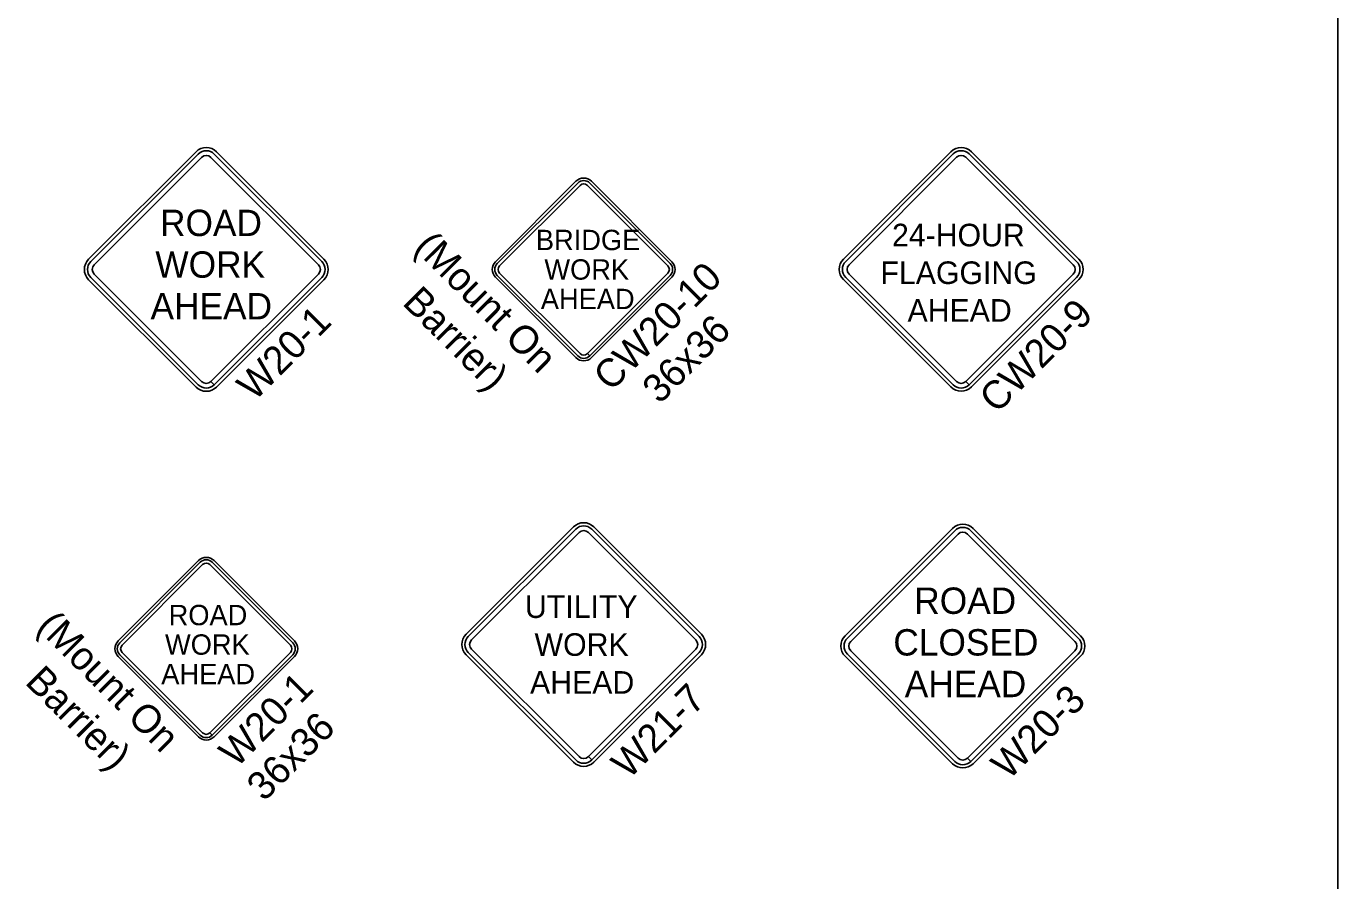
# Model space of a CAD drawing. Extents: x 1458 to 4498, y 17709 to 24109.
# Drawn here: x 2883 to 3578, y 22648 to 23102 of the extents above; entities that cross this region are included whole.
import ezdxf

# ---------------------------------------------------------------- set-up
doc = ezdxf.new("R2010")
doc.units = 0
doc.layers.add('P_ODOT_PLAN_TBlock', color=7, linetype='Continuous')
doc.layers.add('P_TRAF_TCP_General', color=7, linetype='Continuous')

msp = doc.modelspace()

# ---------------------------------------------------------------- linework, layer by layer
at = {"layer": 'P_ODOT_PLAN_TBlock'}
msp.add_line((3578.44, 23153.55), (3578.44, 22109.14), dxfattribs=at)
at = {"layer": 'P_TRAF_TCP_General'}
for p, q in [((2972.81, 23035.32), (2915.81, 22978.32)), ((3040.67, 22978.32), (2983.66, 23035.32)), ((3373.24, 23035.37), (3316.23, 22978.36)), ((3441.09, 22978.36), (3384.09, 23035.37)), ((2974, 23034.14), (2916.99, 22977.13)), ((2974, 23034.14), (2916.99, 22977.13)), ((2974, 23034.14), (2916.99, 22977.13)), ((2918.76, 22975.37), (2975.76, 23032.37)), ((2918.76, 22975.37), (2975.76, 23032.37)), ((2980.71, 23032.37), (3037.72, 22975.37)), ((2980.71, 23032.37), (3037.72, 22975.37)), ((3039.49, 22977.13), (2982.48, 23034.14)), ((3039.49, 22977.13), (2982.48, 23034.14)), ((3039.49, 22977.13), (2982.48, 23034.14)), ((3374.42, 23034.18), (3317.42, 22977.18)), ((3319.18, 22975.41), (3376.19, 23032.42)), ((3381.14, 23032.42), (3438.14, 22975.41)), ((3439.91, 22977.18), (3382.9, 23034.18)), ((3174.34, 23019.69), (3131.65, 22977)), ((3175.26, 23018.77), (3132.56, 22976.08)), ((3175.26, 23018.77), (3132.56, 22976.08)), ((3133.8, 22974.84), (3176.49, 23017.53)), ((3180.38, 23017.53), (3223.07, 22974.84)), ((3224.31, 22976.08), (3181.62, 23018.77)), ((3224.31, 22976.08), (3181.62, 23018.77)), ((3225.23, 22977), (3182.54, 23019.69)), ((2915.81, 22967.47), (2972.81, 22910.46)), ((2916.99, 22968.65), (2974, 22911.65)), ((2916.99, 22968.65), (2974, 22911.65)), ((2916.99, 22968.65), (2974, 22911.65)), ((2975.76, 22913.41), (2918.76, 22970.42)), ((2975.76, 22913.41), (2918.76, 22970.42)), ((3037.72, 22970.42), (2980.73, 22913.43)), ((3037.72, 22970.42), (2980.73, 22913.43)), ((2982.48, 22911.65), (3039.49, 22968.65)), ((2982.5, 22911.66), (3039.49, 22968.65)), ((2982.5, 22911.66), (3039.49, 22968.65)), ((2983.66, 22910.46), (3040.67, 22967.47)), ((3131.65, 22968.8), (3174.34, 22926.1)), ((3132.56, 22969.72), (3175.26, 22927.02)), ((3132.56, 22969.72), (3175.26, 22927.02)), ((3176.49, 22928.26), (3133.8, 22970.95)), ((3223.07, 22970.95), (3180.39, 22928.27)), ((3181.62, 22927.02), (3224.31, 22969.72)), ((3181.63, 22927.04), (3224.31, 22969.72)), ((3182.54, 22926.11), (3225.23, 22968.8)), ((3316.23, 22967.51), (3373.24, 22910.51)), ((3317.42, 22968.7), (3374.42, 22911.69)), ((3376.19, 22913.46), (3319.18, 22970.46)), ((3438.14, 22970.46), (3381.15, 22913.48)), ((3382.92, 22911.71), (3439.91, 22968.7)), ((3384.09, 22910.51), (3441.09, 22967.51)), ((3181.62, 22927.02), (3180.38, 22928.26)), ((3180.39, 22928.27), (3181.63, 22927.04)), ((2982.48, 22911.65), (2980.71, 22913.41)), ((2982.48, 22911.65), (2980.71, 22913.41)), ((2980.73, 22913.43), (2982.5, 22911.66)), ((2980.73, 22913.43), (2982.5, 22911.66)), ((3382.9, 22911.69), (3381.14, 22913.46)), ((3382.9, 22911.69), (3381.14, 22913.46)), ((3381.15, 22913.48), (3382.92, 22911.71)), ((3173.01, 22836.24), (3116.01, 22779.24)), ((3174.2, 22835.06), (3117.19, 22778.05)), ((3174.2, 22835.06), (3117.19, 22778.05)), ((3174.2, 22835.06), (3117.19, 22778.05)), ((3118.96, 22776.29), (3175.96, 22833.29)), ((3118.96, 22776.29), (3175.96, 22833.29)), ((3180.91, 22833.29), (3237.92, 22776.29)), ((3180.91, 22833.29), (3237.92, 22776.29)), ((3239.68, 22778.05), (3182.68, 22835.06)), ((3239.68, 22778.05), (3182.68, 22835.06)), ((3239.68, 22778.05), (3182.68, 22835.06)), ((3240.87, 22779.24), (3183.86, 22836.24)), ((3374.12, 22835.43), (3317.11, 22778.42)), ((3375.3, 22834.25), (3318.3, 22777.24)), ((3440.79, 22777.24), (3383.78, 22834.25)), ((3441.97, 22778.42), (3384.97, 22835.43)), ((3320.06, 22775.47), (3377.07, 22832.48)), ((3382.02, 22832.48), (3439.02, 22775.47)), ((2974.14, 22818.38), (2931.45, 22775.69)), ((2975.06, 22817.47), (2932.37, 22774.77)), ((2975.06, 22817.47), (2932.37, 22774.77)), ((2933.6, 22773.54), (2976.29, 22816.23)), ((2980.18, 22816.23), (3022.87, 22773.54)), ((3024.11, 22774.77), (2981.42, 22817.47)), ((3024.11, 22774.77), (2981.42, 22817.47)), ((3025.03, 22775.69), (2982.34, 22818.38)), ((3175.96, 22714.33), (3118.96, 22771.34)), ((3175.96, 22714.33), (3118.96, 22771.34)), ((3237.92, 22771.34), (3180.93, 22714.35)), ((3237.92, 22771.34), (3180.93, 22714.35)), ((2931.45, 22767.49), (2974.14, 22724.8)), ((2932.37, 22768.41), (2975.06, 22725.72)), ((2932.37, 22768.41), (2975.06, 22725.72)), ((2976.29, 22726.96), (2933.6, 22769.65)), ((3022.87, 22769.65), (2980.19, 22726.97)), ((2981.42, 22725.72), (3024.11, 22768.41)), ((2981.43, 22725.73), (3024.11, 22768.41)), ((2982.34, 22724.8), (3025.03, 22767.49)), ((3116.01, 22768.39), (3173.01, 22711.38)), ((3117.19, 22769.57), (3174.2, 22712.57)), ((3117.19, 22769.57), (3174.2, 22712.57)), ((3117.19, 22769.57), (3174.2, 22712.57)), ((3182.68, 22712.57), (3239.68, 22769.57)), ((3182.7, 22712.58), (3239.68, 22769.57)), ((3182.7, 22712.58), (3239.68, 22769.57)), ((3183.86, 22711.38), (3240.87, 22768.39)), ((3317.11, 22767.57), (3374.12, 22710.57)), ((3318.3, 22768.76), (3375.3, 22711.75)), ((3377.07, 22713.52), (3320.06, 22770.53)), ((3439.02, 22770.53), (3382.03, 22713.54)), ((3383.8, 22711.77), (3440.79, 22768.76)), ((3384.97, 22710.57), (3441.97, 22767.57)), ((2981.42, 22725.72), (2980.18, 22726.96)), ((2980.19, 22726.97), (2981.43, 22725.73)), ((3182.68, 22712.57), (3180.91, 22714.33)), ((3182.68, 22712.57), (3180.91, 22714.33)), ((3180.93, 22714.35), (3182.7, 22712.58)), ((3180.93, 22714.35), (3182.7, 22712.58)), ((3383.78, 22711.75), (3382.02, 22713.52)), ((3383.78, 22711.75), (3382.02, 22713.52)), ((3382.03, 22713.54), (3383.8, 22711.77)), ((3382.03, 22713.54), (3383.8, 22711.77))]:
    msp.add_line(p, q, dxfattribs=at)
for centre, radius, start, end in [((2978.24, 23029.9), 7.67, 45, 135), ((2978.24, 23029.9), 6, 45, 135), ((2978.24, 23029.9), 6, 45, 135), ((2978.24, 23029.9), 6, 45, 135), ((3378.66, 23029.94), 7.67, 45, 135), ((3378.66, 23029.94), 6, 45, 135), ((2978.24, 23029.9), 3.5, 45, 135), ((2978.24, 23029.9), 3.5, 45, 135), ((3378.66, 23029.94), 3.5, 45, 135), ((3178.44, 23015.59), 5.8, 45, 135), ((3178.44, 23015.59), 4.5, 45, 135), ((3178.44, 23015.59), 4.5, 45, 135), ((3178.44, 23015.59), 2.75, 45, 135), ((2921.23, 22972.89), 7.67, 135, 225), ((2921.23, 22972.89), 6, 135, 225), ((2921.23, 22972.89), 6, 135, 225), ((2921.23, 22972.89), 6, 135, 225), ((2921.23, 22972.89), 3.5, 135, 225), ((2921.23, 22972.89), 3.5, 135, 225), ((3035.24, 22972.89), 3.5, 315, 45), ((3035.24, 22972.89), 3.5, 315, 45), ((3035.24, 22972.89), 6, 315, 45), ((3035.24, 22972.89), 6, 315, 45), ((3035.24, 22972.89), 6, 315, 45), ((3035.24, 22972.89), 7.67, 315, 45), ((3135.75, 22972.9), 5.8, 135, 225), ((3135.75, 22972.9), 4.5, 135, 225), ((3135.75, 22972.9), 4.5, 135, 225), ((3135.75, 22972.9), 2.75, 135, 225), ((3221.13, 22972.9), 2.75, 315, 45), ((3221.13, 22972.9), 4.5, 315, 45), ((3221.13, 22972.9), 4.5, 315, 45), ((3221.13, 22972.9), 5.8, 315, 45), ((3321.66, 22972.94), 7.67, 135, 225), ((3321.66, 22972.94), 6, 135, 225), ((3321.66, 22972.94), 3.5, 135, 225), ((3435.67, 22972.94), 3.5, 315, 45), ((3435.67, 22972.94), 6, 315, 45), ((3435.67, 22972.94), 7.67, 315, 45), ((3178.44, 22930.2), 5.8, 225, 315), ((3178.44, 22930.2), 4.5, 225, 315), ((3178.44, 22930.2), 4.5, 225, 315), ((3178.44, 22930.2), 2.75, 225, 315), ((2978.24, 22915.89), 7.67, 225, 315), ((2978.24, 22915.89), 6, 225, 315), ((2978.24, 22915.89), 6, 225, 315), ((2978.24, 22915.89), 6, 225, 315), ((2978.24, 22915.89), 3.5, 225, 315), ((2978.24, 22915.89), 3.5, 225, 315), ((3378.66, 22915.93), 7.67, 225, 315), ((3378.66, 22915.93), 6, 225, 315), ((3378.66, 22915.93), 6, 225, 315), ((3378.66, 22915.93), 3.5, 225, 315), ((3178.44, 22830.82), 7.67, 45, 135), ((3178.44, 22830.82), 6, 45, 135), ((3178.44, 22830.82), 6, 45, 135), ((3178.44, 22830.82), 6, 45, 135), ((3178.44, 22830.82), 3.5, 45, 135), ((3178.44, 22830.82), 3.5, 45, 135), ((3379.54, 22830), 7.67, 45, 135), ((3379.54, 22830), 6, 45, 135), ((3379.54, 22830), 3.5, 45, 135), ((2978.24, 22814.28), 5.8, 45, 135), ((2978.24, 22814.28), 4.5, 45, 135), ((2978.24, 22814.28), 4.5, 45, 135), ((2978.24, 22814.28), 2.75, 45, 135), ((3121.43, 22773.81), 7.67, 135, 225), ((3121.43, 22773.81), 6, 135, 225), ((3121.43, 22773.81), 6, 135, 225), ((3121.43, 22773.81), 6, 135, 225), ((3235.44, 22773.81), 6, 315, 45), ((3235.44, 22773.81), 6, 315, 45), ((3235.44, 22773.81), 6, 315, 45), ((3235.44, 22773.81), 7.67, 315, 45), ((3322.54, 22773), 7.67, 135, 225), ((3436.55, 22773), 7.67, 315, 45), ((2935.55, 22771.59), 5.8, 135, 225), ((2935.55, 22771.59), 4.5, 135, 225), ((2935.55, 22771.59), 4.5, 135, 225), ((2935.55, 22771.59), 2.75, 135, 225), ((3020.93, 22771.59), 2.75, 315, 45), ((3020.93, 22771.59), 4.5, 315, 45), ((3020.93, 22771.59), 4.5, 315, 45), ((3020.93, 22771.59), 5.8, 315, 45), ((3121.43, 22773.81), 3.5, 135, 225), ((3121.43, 22773.81), 3.5, 135, 225), ((3235.44, 22773.81), 3.5, 315, 45), ((3235.44, 22773.81), 3.5, 315, 45), ((3322.54, 22773), 6, 135, 225), ((3322.54, 22773), 3.5, 135, 225), ((3436.55, 22773), 3.5, 315, 45), ((3436.55, 22773), 6, 315, 45), ((2978.24, 22728.9), 5.8, 225, 315), ((2978.24, 22728.9), 4.5, 225, 315), ((2978.24, 22728.9), 4.5, 225, 315), ((2978.24, 22728.9), 2.75, 225, 315), ((3178.44, 22716.81), 7.67, 225, 315), ((3178.44, 22716.81), 6, 225, 315), ((3178.44, 22716.81), 6, 225, 315), ((3178.44, 22716.81), 6, 225, 315), ((3178.44, 22716.81), 3.5, 225, 315), ((3178.44, 22716.81), 3.5, 225, 315), ((3379.54, 22715.99), 7.67, 225, 315), ((3379.54, 22715.99), 6, 225, 315), ((3379.54, 22715.99), 3.5, 225, 315)]:
    msp.add_arc(centre, radius, start, end, dxfattribs=at)

# ---------------------------------------------------------------- texts
for s, height, p in [('ROAD', 13.994, (2953.7, 22990.62)), ('BRIDGE', 10.8, (3153.08, 22983.15)), ('24-HOUR', 11.995, (3341.99, 22985.15)), ('WORK', 13.994, (2951.22, 22968.51)), ('WORK', 10.8, (3157.59, 22967.49)), ('FLAGGING', 11.995, (3335.88, 22965.16)), ('AHEAD', 13.994, (2948.65, 22946.4)), ('AHEAD', 10.8, (3155.69, 22951.83)), ('AHEAD', 11.995, (3350.23, 22945.16)), ('UTILITY', 12, (3147.28, 22787.93)), ('ROAD', 13.994, (3353.79, 22790.09)), ('ROAD', 10.8, (2958.27, 22784.07)), ('WORK', 10.8, (2956.35, 22768.41)), ('WORK', 12, (3152.36, 22767.81)), ('CLOSED', 13.994, (3342.69, 22767.98)), ('AHEAD', 10.8, (2954.35, 22752.75)), ('AHEAD', 12, (3149.98, 22747.7)), ('AHEAD', 13.994, (3348.74, 22745.87))]:
    msp.add_text(s, height=height, dxfattribs=at).set_placement(p)
for s, rotation, p in [('(Mount On', 315, (3087.88, 22983.89)), ('CW20-10', 45, (3192.84, 22907.6)), ('Barrier)', 315, (3081.77, 22954.66)), ('W20-1', 45, (3003.75, 22902.53)), ('CW20-9', 45, (3397.56, 22895.96)), ('36x36', 45, (3218.74, 22901)), ('(Mount On', 315, (2887.68, 22782.59)), ('Barrier)', 315, (2881.57, 22753.36)), ('W20-1', 45, (2994.26, 22707.92)), ('W21-7', 45, (3202.38, 22701.87)), ('W20-3', 45, (3403.84, 22701.42)), ('36x36', 45, (3008.9, 22690.04))]:
    msp.add_text(s, height=14.994, rotation=rotation, dxfattribs=at).set_placement(p)

doc.saveas('drawing.dxf')
